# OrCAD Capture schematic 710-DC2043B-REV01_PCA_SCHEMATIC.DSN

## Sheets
1 PAGE2: size Custom; note: LEAD ACID BATTERY BALANCER
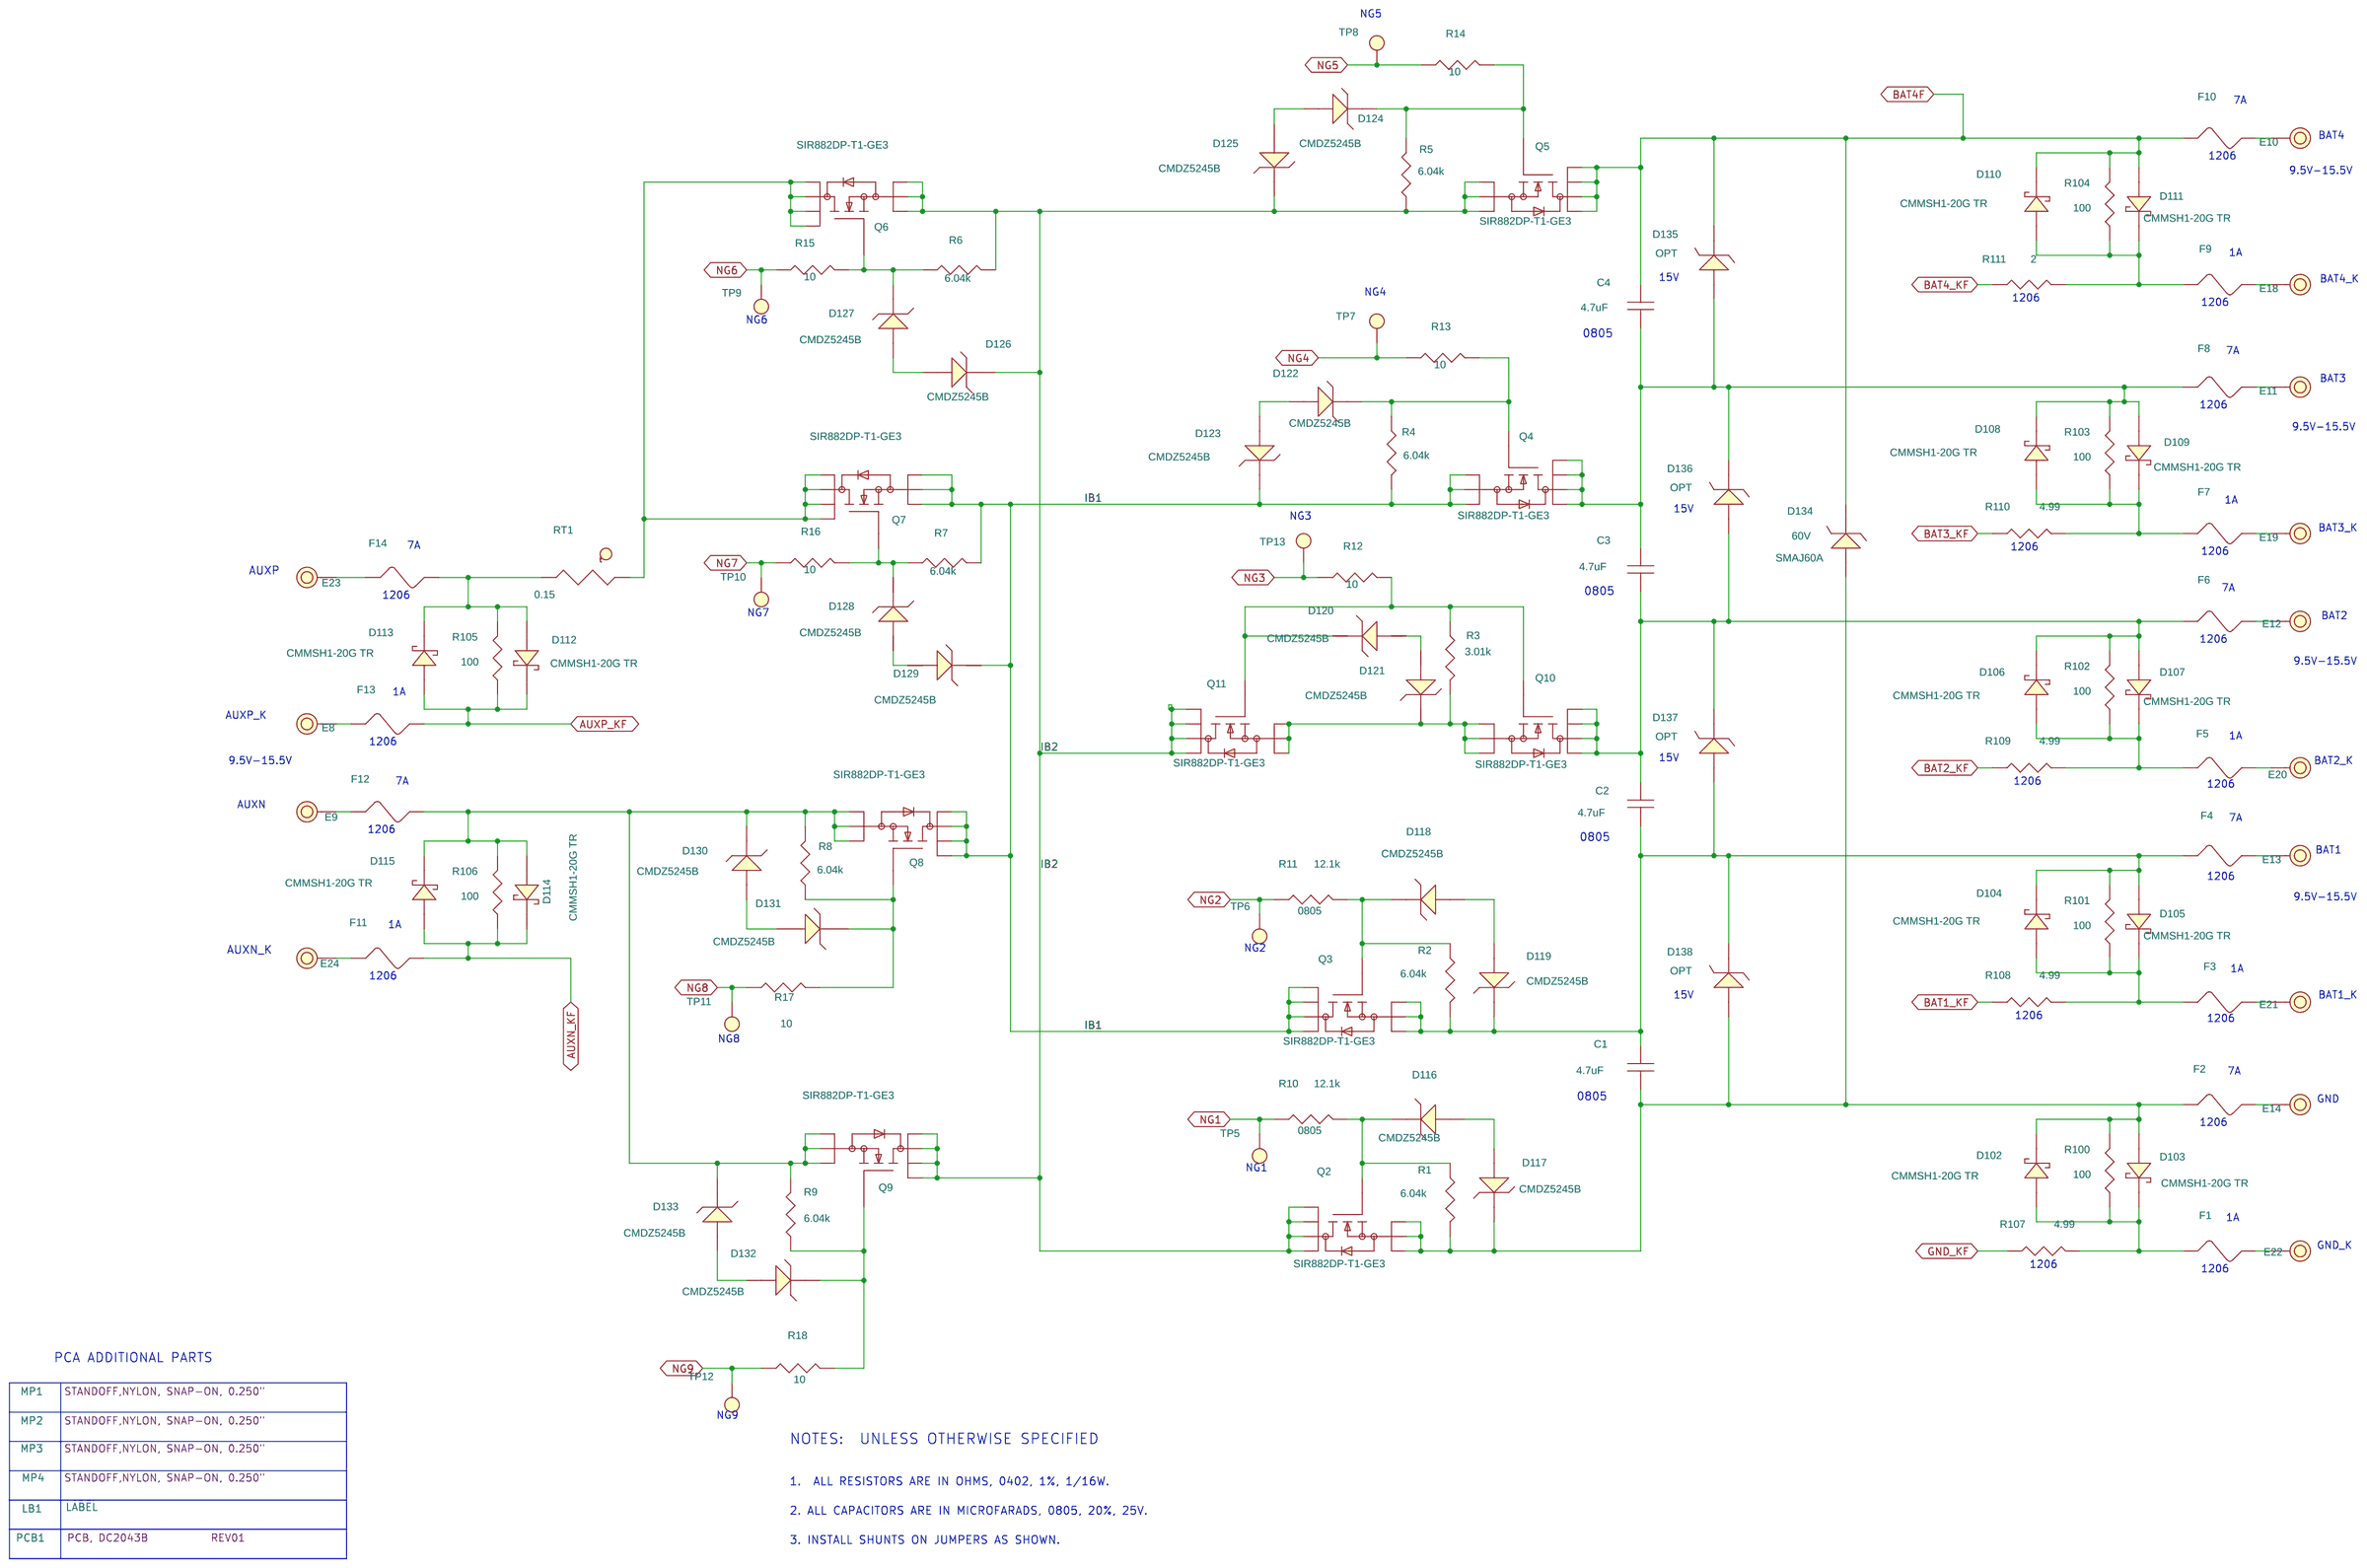
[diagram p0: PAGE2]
2 PAGE1: size Custom
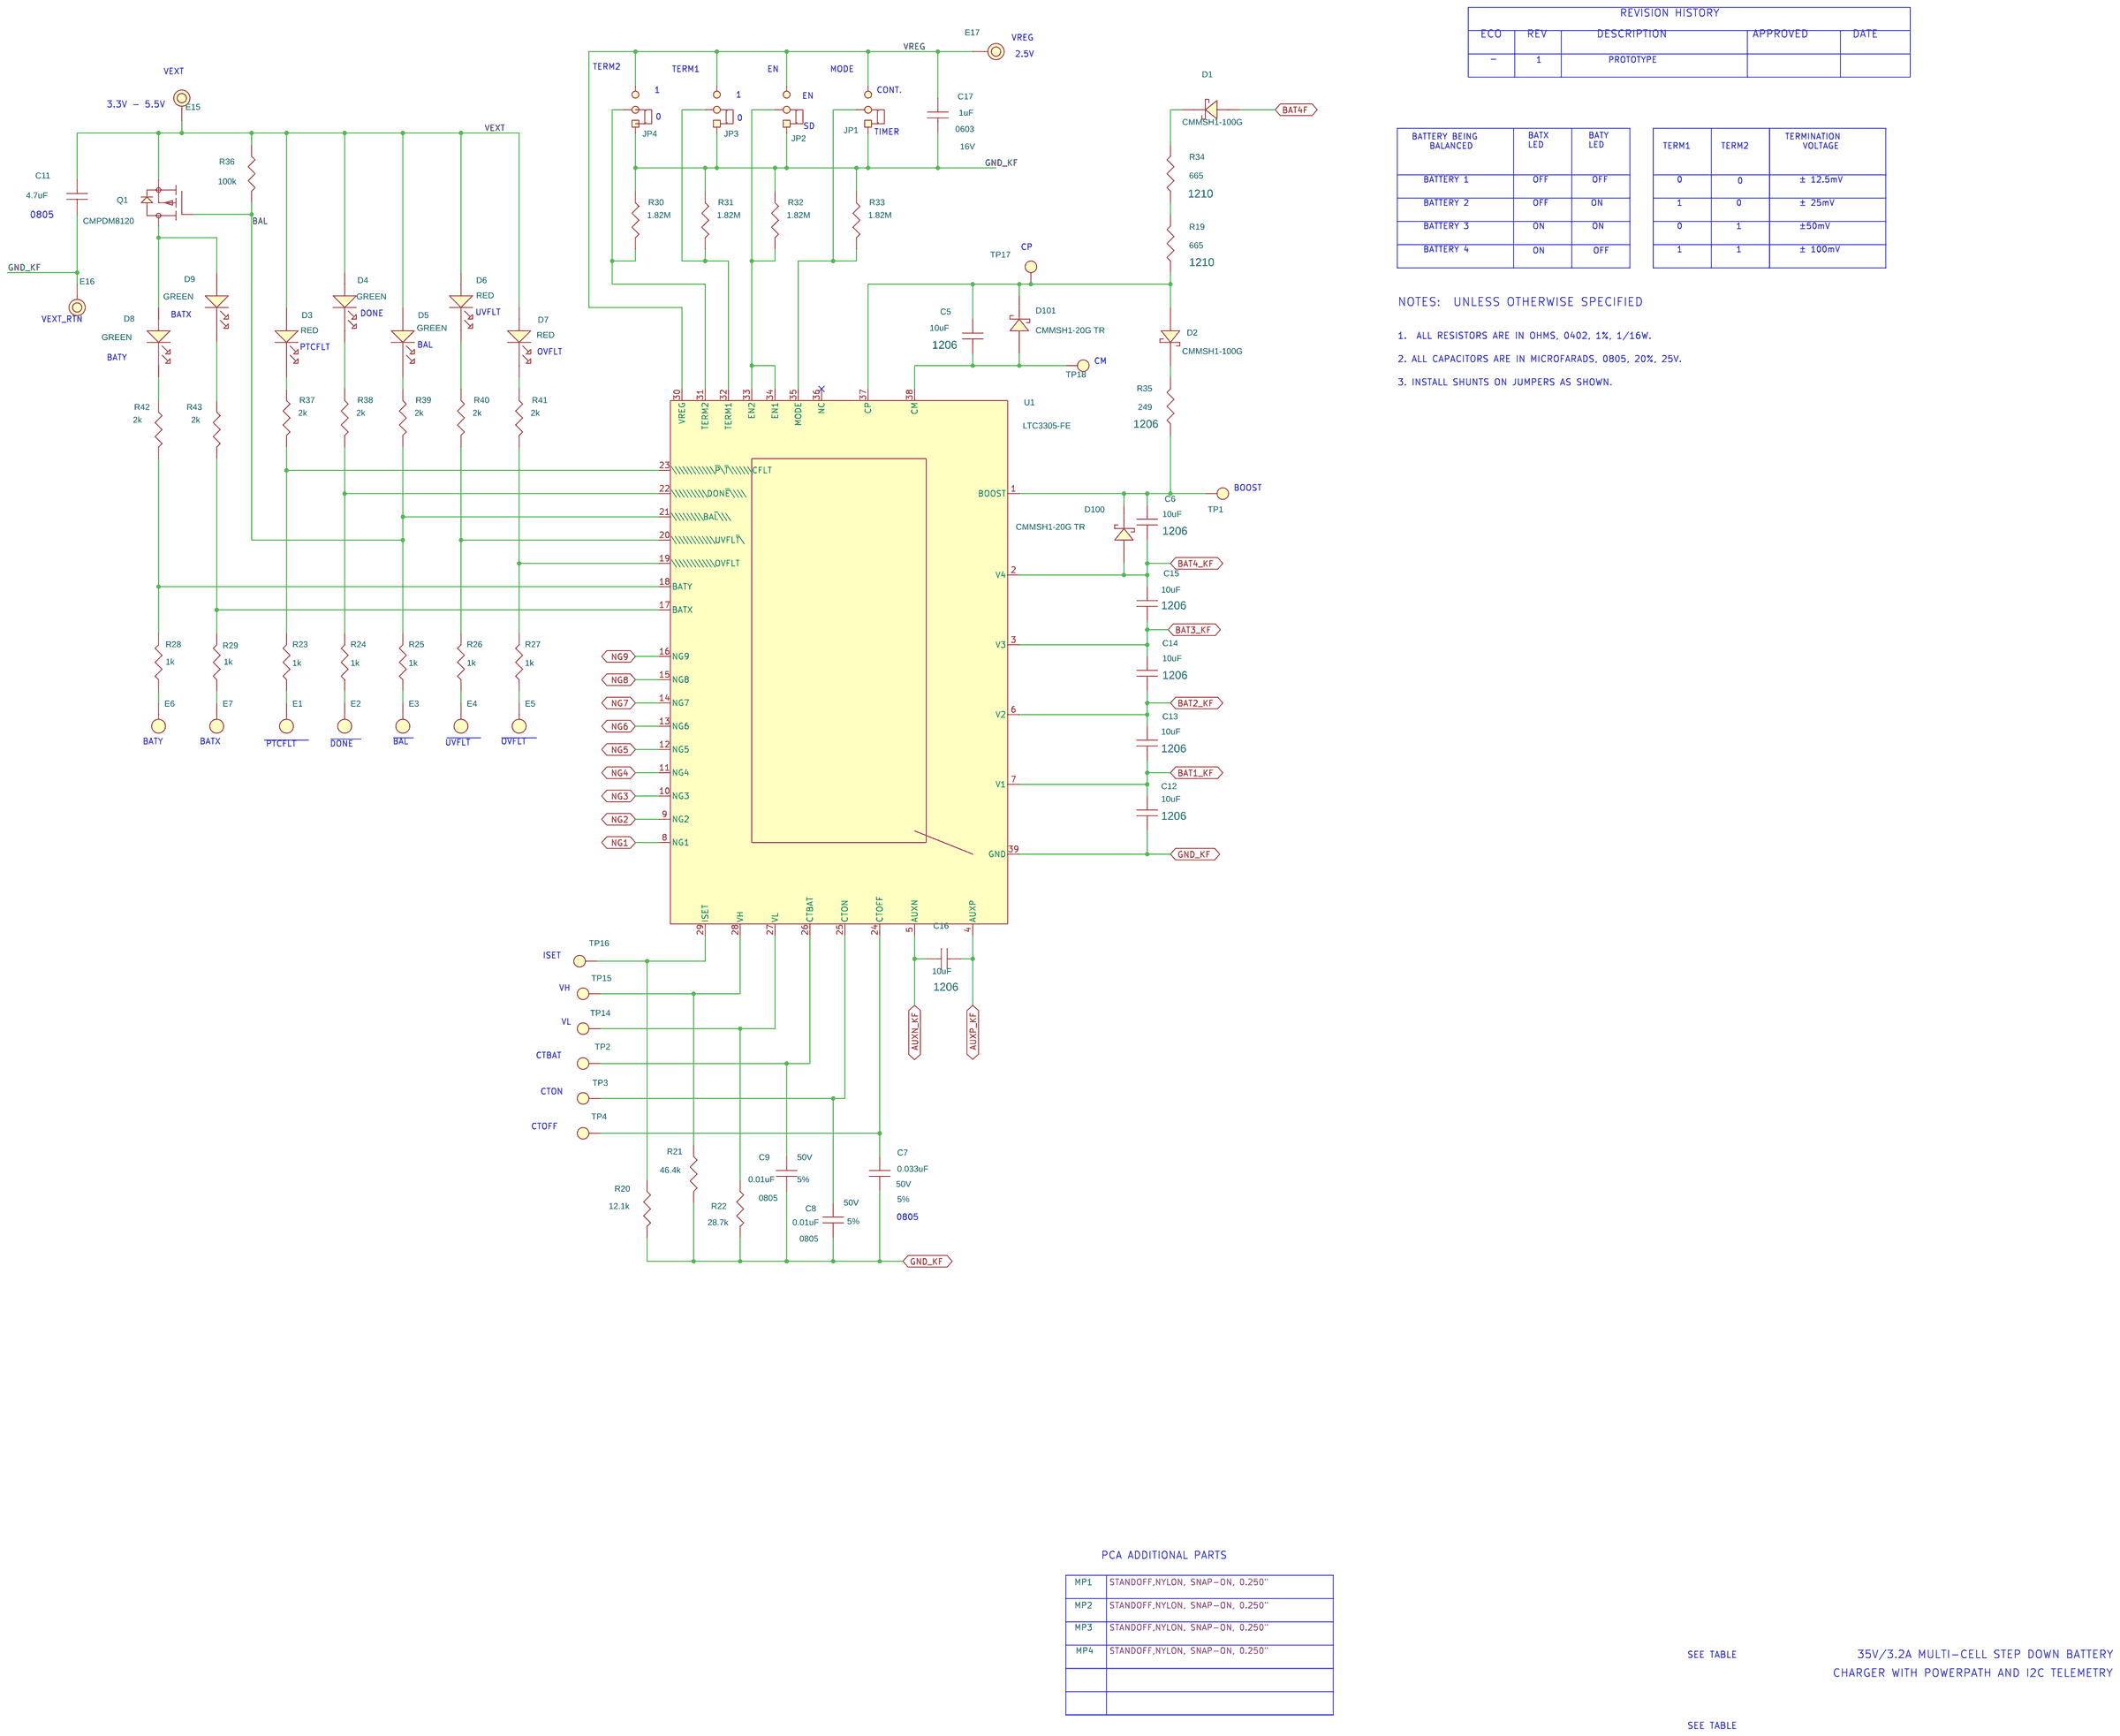
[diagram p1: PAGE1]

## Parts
sheet PAGE1
C5  10uF  [CC1206M]
C6  10uF  [CC1206M]
C7  0.033uF  [CC0805M]
C8  0.01uF  [CC0805M]
C9  0.01uF  [CC0805M]
C11  4.7uF  [CC0805M]
C12  10uF  [CC1206M]
C13  10uF  [CC1206M]
C14  10uF  [CC1206M]
C15  10uF  [CC1206M]
C16  10uF  [CC1206M]
C17  1uF  [CC0603M]
D1  CMMSH1-100G  [SOD-123F]
D2  CMMSH1-100G  [SOD-123F]
D3  RED  [LED-LTST-C193KRKT-5A]
D4  GREEN  [LED-LTST-C193KGKT-5A]
D5  GREEN  [LED-LTST-C193KGKT-5A]
D6  RED  [LED-LTST-C193KRKT-5A]
D7  RED  [LED-LTST-C193KRKT-5A]
D8  GREEN  [LED-LTST-C193KGKT-5A]
D9  GREEN  [LED-LTST-C193KGKT-5A]
D100  CMMSH1-20G TR  [SOD-123F]
D101  CMMSH1-20G TR  [SOD-123F]
E1  TEST POINT  [MILLMAX2308]
E2  TEST POINT  [MILLMAX2308]
E3  TEST POINT  [MILLMAX2308]
E4  TEST POINT  [MILLMAX2308]
E5  TEST POINT  [MILLMAX2308]
E6  TEST POINT  [MILLMAX2308]
E7  TEST POINT  [MILLMAX2308]
E15  TEST POINT  [MILLMAX2501]
E16  TEST POINT  [MILLMAX2501]
E17  TEST POINT  [MILLMAX2501]
JP1  HDR  [HD1X3-079]
JP2  HDR  [HD1X3-079]
JP3  HDR  [HD1X3-079]
JP4  HDR  [HD1X3-079]
MP9  STANDOFF  [MTG-8831]
MP10  STANDOFF  [MTG-8831]
MP11  STANDOFF  [MTG-8831]
MP12  STANDOFF  [MTG-8831]
Q1  CMPDM8120  [SOT-23]
R19  665  [CR1210M]
R20  12.1k  [CR0402M]
R21  46.4k  [CR0402M]
R22  28.7k  [CR0402M]
R23  1k  [CR0402M]
R24  1k  [CR0402M]
R25  1k  [CR0402M]
R26  1k  [CR0402M]
R27  1k  [CR0402M]
R28  1k  [CR0402M]
R29  1k  [CR0402M]
R30  1.82M  [CR0402M]
R31  1.82M  [CR0402M]
R32  1.82M  [CR0402M]
R33  1.82M  [CR0402M]
R34  665  [CR1210M]
R35  249  [CR1206M]
R36  100k  [CR0402M]
R37  2k  [CR0402M]
R38  2k  [CR0402M]
R39  2k  [CR0402M]
R40  2k  [CR0402M]
R41  2k  [CR0402M]
R42  2k  [CR0402M]
R43  2k  [CR0402M]
TP1  TEST PAD  [PADSTYLE7]
TP2  TEST PAD  [PADSTYLE7]
TP3  TEST PAD  [PADSTYLE7]
TP4  TEST PAD  [PADSTYLE7]
TP14  TEST PAD  [PADSTYLE7]
TP15  TEST PAD  [PADSTYLE7]
TP16  TEST PAD  [PADSTYLE7]
TP17  TEST PAD  [PADSTYLE7]
TP18  TEST PAD  [PADSTYLE7]
U1  LTC3305-FE  [LTC-FE-38-1772]
XJP1  SHUNT
XJP2  SHUNT
XJP3  SHUNT
XJP4  SHUNT
sheet PAGE2
C1  4.7uF  [CC0805M]
C2  4.7uF  [CC0805M]
C3  4.7uF  [CC0805M]
C4  4.7uF  [CC0805M]
D102  CMMSH1-20G TR  [SOD-123F]
D103  CMMSH1-20G TR  [SOD-123F]
D104  CMMSH1-20G TR  [SOD-123F]
D105  CMMSH1-20G TR  [SOD-123F]
D106  CMMSH1-20G TR  [SOD-123F]
D107  CMMSH1-20G TR  [SOD-123F]
D108  CMMSH1-20G TR  [SOD-123F]
D109  CMMSH1-20G TR  [SOD-123F]
D110  CMMSH1-20G TR  [SOD-123F]
D111  CMMSH1-20G TR  [SOD-123F]
D112  CMMSH1-20G TR  [SOD-123F]
D113  CMMSH1-20G TR  [SOD-123F]
D114  CMMSH1-20G TR  [SOD-123F]
D115  CMMSH1-20G TR  [SOD-123F]
D116  CMDZ5245B  [CENTRAL-SEMI-SOD-323]
D117  CMDZ5245B  [CENTRAL-SEMI-SOD-323]
D118  CMDZ5245B  [CENTRAL-SEMI-SOD-323]
D119  CMDZ5245B  [CENTRAL-SEMI-SOD-323]
D120  CMDZ5245B  [CENTRAL-SEMI-SOD-323]
D121  CMDZ5245B  [CENTRAL-SEMI-SOD-323]
D122  CMDZ5245B  [CENTRAL-SEMI-SOD-323]
D123  CMDZ5245B  [CENTRAL-SEMI-SOD-323]
D124  CMDZ5245B  [CENTRAL-SEMI-SOD-323]
D125  CMDZ5245B  [CENTRAL-SEMI-SOD-323]
D126  CMDZ5245B  [CENTRAL-SEMI-SOD-323]
D127  CMDZ5245B  [CENTRAL-SEMI-SOD-323]
D128  CMDZ5245B  [CENTRAL-SEMI-SOD-323]
D129  CMDZ5245B  [CENTRAL-SEMI-SOD-323]
D130  CMDZ5245B  [CENTRAL-SEMI-SOD-323]
D131  CMDZ5245B  [CENTRAL-SEMI-SOD-323]
D132  CMDZ5245B  [CENTRAL-SEMI-SOD-323]
D133  CMDZ5245B  [CENTRAL-SEMI-SOD-323]
D134  SMAJ60A  [DIODESINC-SMA]
D135  OPT  [DIODESINC-SMA]
D136  OPT  [DIODESINC-SMA]
D137  OPT  [DIODESINC-SMA]
D138  OPT  [DIODESINC-SMA]
E8  TEST POINT  [MILLMAX2501]
E9  TEST POINT  [MILLMAX2501]
E10  TEST POINT  [MILLMAX2501]
E11  TEST POINT  [MILLMAX2501]
E12  TEST POINT  [MILLMAX2501]
E13  TEST POINT  [MILLMAX2501]
E14  TEST POINT  [MILLMAX2501]
E18  TEST POINT  [MILLMAX2501]
E19  TEST POINT  [MILLMAX2501]
E20  TEST POINT  [MILLMAX2501]
E21  TEST POINT  [MILLMAX2501]
E22  TEST POINT  [MILLMAX2501]
E23  TEST POINT  [MILLMAX2501]
E24  TEST POINT  [MILLMAX2501]
F1  FUSE  [CR1206M]
F2  FUSE  [CR1206M]
F3  FUSE  [CR1206M]
F4  FUSE  [CR1206M]
F5  FUSE  [CR1206M]
F6  FUSE  [CR1206M]
F7  FUSE  [CR1206M]
F8  FUSE  [CR1206M]
F9  FUSE  [CR1206M]
F10  FUSE  [CR1206M]
F11  FUSE  [CR1206M]
F12  FUSE  [CR1206M]
F13  FUSE  [CR1206M]
F14  FUSE  [CR1206M]
LB1  LABEL  [895-0154_REV01]
MP1  STANDOFF  [MTG-8831]
MP2  STANDOFF  [MTG-8831]
MP3  STANDOFF  [MTG-8831]
MP4  STANDOFF  [MTG-8831]
PCB1  PCB, DC2043B
Q2  SIR882DP-T1-GE3  [POWERPAKSO-8]
Q3  SIR882DP-T1-GE3  [POWERPAKSO-8]
Q4  SIR882DP-T1-GE3  [POWERPAKSO-8]
Q5  SIR882DP-T1-GE3  [POWERPAKSO-8]
Q6  SIR882DP-T1-GE3  [POWERPAKSO-8]
Q7  SIR882DP-T1-GE3  [POWERPAKSO-8]
Q8  SIR882DP-T1-GE3  [POWERPAKSO-8]
Q9  SIR882DP-T1-GE3  [POWERPAKSO-8]
Q10  SIR882DP-T1-GE3  [POWERPAKSO-8]
Q11  SIR882DP-T1-GE3  [POWERPAKSO-8]
R1  6.04k  [CR0402M]
R2  6.04k  [CR0402M]
R3  3.01k  [CR0402M]
R4  6.04k  [CR0402M]
R5  6.04k  [CR0402M]
R6  6.04k  [CR0402M]
R7  6.04k  [CR0402M]
R8  6.04k  [CR0402M]
R9  6.04k  [CR0402M]
R10  12.1k  [CR0805M]
R11  12.1k  [CR0805M]
R12  10  [CR0402M]
R13  10  [CR0402M]
R14  10  [CR0402M]
R15  10  [CR0402M]
R16  10  [CR0402M]
R17  10  [CR0402M]
R18  10  [CR0402M]
R100  100  [CR0402M]
R101  100  [CR0402M]
R102  100  [CR0402M]
R103  100  [CR0402M]
R104  100  [CR0402M]
R105  100  [CR0402M]
R106  100  [CR0402M]
R107  4.99  [CR1206M]
R108  4.99  [CR1206M]
R109  4.99  [CR1206M]
R110  4.99  [CR1206M]
R111  2  [CR1206M]
RT1  0.15  [PTC-PTGLASARR27M1B51B0]
TP5  TEST PAD  [PADSTYLE7]
TP6  TEST PAD  [PADSTYLE7]
TP7  TEST PAD  [PADSTYLE7]
TP8  TEST PAD  [PADSTYLE7]
TP9  TEST PAD  [PADSTYLE7]
TP10  TEST PAD  [PADSTYLE7]
TP11  TEST PAD  [PADSTYLE7]
TP12  TEST PAD  [PADSTYLE7]
TP13  TEST PAD  [PADSTYLE7]

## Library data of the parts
C5 C6 C12-C16 = CAP: CAP.,10uF,X7R,25V,20%,1206; CLASS: DISCRETE; Dielectric Type: X7R; FPLIST: CC1206N,CC1206L,CC1206M; Manufacturer: TDK; Manufacturer PN: C3216X7R1E106M160AB; PART_NUMBER: 150-2302; Package Size: 1206; Rated Voltage: 25V; Tolerance: 20%
C7 = CAP: CAP.,0.033uF,C0G,50V,5%,0805,AUTOMOTIVE; CLASS: DISCRETE; Dielectric Type: C0G; FPLIST: CC0805N,CC0805L,CC0805M; Manufacturer: TDK; Manufacturer PN: CGA4J2C0G1H333J125AA; PART_NUMBER: 150-2300; Package Size: 0805; Package Type: Surface Mount, MLCC; Rated Voltage: 50V; Temperature Coefficient: C0G, NP0; Tolerance: 5%; UserField01: AUTOMOTIVE
C8 C9 = CAP: CAP.,0.01uF,C0G,50V,5%,0805,AUTOMOTIVE; CLASS: DISCRETE; Dielectric Type: C0G; FPLIST: CC0805N,CC0805L,CC0805M; Manufacturer: TDK; Manufacturer PN: CGA4C2C0G1H103J060AA; PART_NUMBER: 150-2301; Package Size: 0805; Package Type: SMD; Rated Voltage: 50V; Tolerance: 5%; UserField01: AUTOMOTIVE
C1-C4 C11 = CAP: CAP.,4.7uF,X7R,25V,10%,0805; CLASS: DISCRETE; Dielectric Type: X7R; FPLIST: CC0805N,CC0805L,CC0805M; Manufacturer: MURATA; Manufacturer PN: GRM21BR71E475KA73L; PART_NUMBER: 150-3337; Package Size: 0805; Rated Voltage: 25V; Tolerance: 10%
C17 = CAP: CAP.,1uF,X7R,16V,10%,0603; CLASS: DISCRETE; Dielectric Type: X7R; FPLIST: CC0603N,CC0603L,CC0603M; Manufacturer: MURATA; Manufacturer PN: GRM188R71C105KA12D; PART_NUMBER: 150-0179; Package Size: 0603; Rated Voltage: 16V; Tolerance: 10%
D1 D2 = DIODE_SCHOTTKY_A_ALT: DIODE,SCHOTTKY,100V,1A,SOD-123F; CLASS: DISCRETE; Manufacturer: CENTRAL SEMI; Manufacturer PN: CMMSH1-100G TR LEAD FREE; PART_NUMBER: 210-0147; Rated Voltage: 100V
D3 D6 D7 = LED_ALT: LED,RED,CLEAR,0603 SMD; CLASS: DISCRETE; Manufacturer: LITE-ON TECHNOLOGY CORP; Manufacturer PN: LTST-C193KRKT-5A; PART_NUMBER: 270-0070; Package Size: 0603 (1608 Metric)
D4 D5 D8 D9 = LED_ALT: LED,GREEN,CLEAR,0603 SMD; CLASS: DISCRETE; Manufacturer: LITE-ON TECHNOLOGY CORP; Manufacturer PN: LTST-C193KGKT-5A; PART_NUMBER: 270-0054; Package Size: 0603 (1608 Metric)
D100-D115 = DIODE_SCHOTTKY_A_ALT: DIODE,SCHOTTKY,20V,1A,SOD-123F; CLASS: DISCRETE; Manufacturer: CENTRAL SEMI; Manufacturer PN: CMMSH1-20G TR LEAD FREE; PART_NUMBER: 210-0222; Rated Voltage: 20V
E1-E7 = TEST_POINT_.156_MILL-MAX_2308: TEST POINT,TURRET,0.064" MTG. HOLE,0.125" THICK PCB; CLASS: IO; Manufacturer: MILL-MAX; Manufacturer PN: 2308-4-00-80-00-00-07-0; PART_NUMBER: 260-0008
E8-E24 = TESTPOINT_.219_MILL-MAX_2501: TEST POINT,TURRET,0.094",MTG. HOLE; CLASS: IO; Manufacturer: MILL-MAX; Manufacturer PN: 2501-2-00-80-00-00-07-0; PART_NUMBER: 260-0003
JP1-JP4 = 3_PIN_HEADER_.079_SINGLE_ROW_D: CONN.,HDR,MALE,1x3,2mm,THT, STR; CLASS: IO; Manufacturer: Wurth Elektronik; Manufacturer PN: 62000311121; PART_NUMBER: 250-0484
MP1-MP4 MP9-MP12 = BLANK_MECHANICAL_PART: STANDOFF,NYLON, SNAP-ON, 0.250"; CLASS: MECHANICAL PART; Manufacturer: KEYSTONE; Manufacturer PN: 8831; PART_NUMBER: 763-0006
Q1 = CMPDM8120: XSTR.,MOSFET, P-CH,20V,0.95A,SOT-23; CLASS: DISCRETE; Manufacturer: CENTRAL SEMI; Manufacturer PN: CMPDM8120 PBFREE; PART_NUMBER: 240-0228
R19 R34 = RES: RES.,665 OHMS,1%,1/2W,1210; CLASS: DISCRETE; FPLIST: CR1210N,CR1210L,CR1210M; Manufacturer: VISHAY; Manufacturer PN: CRCW1210665RFKEA; PART_NUMBER: 100-0544; Package Size: 1210; Rated Power: 1/2W; Temperature Coefficient: 100ppm; Tolerance: 1%
R20 = RES: RES.,12.1k OHMS,1%,1/16W,0402; CLASS: DISCRETE; FPLIST: CR0402N,CR0402L,CR0402M; Manufacturer: VISHAY; Manufacturer PN: CRCW040212K1FKED; PART_NUMBER: 100-2639; Package Size: 0402; Rated Power: 1/16W; Temperature Coefficient: 100ppm/C; Tolerance: 1%
R21 = RES: RES.,46.4k OHMS,1%,1/16W,0402; CLASS: DISCRETE; FPLIST: CR0402N,CR0402L,CR0402M; Manufacturer: VISHAY; Manufacturer PN: CRCW040246K4FKED; PART_NUMBER: 100-2065; Package Size: 0402; Rated Power: 1/16W; Temperature Coefficient: +/-100PPM; Tolerance: 1%
R22 = RES: RES.,28.7k OHMS,1%,1/16W,0402; CLASS: DISCRETE; FPLIST: CR0402N,CR0402L,CR0402M; Manufacturer: VISHAY; Manufacturer PN: CRCW040228K7FKED; PART_NUMBER: 100-0545; Package Size: 0402; Rated Power: 1/16W; Temperature Coefficient: 100ppm; Tolerance: 1%
R23-R29 = RES: RES.,1k OHM,1%,1/16W,0402; CLASS: DISCRETE; FPLIST: CR0402N,CR0402L,CR0402M; Manufacturer: NIC; Manufacturer PN: NRC04F1001TRF; PART_NUMBER: 100-2456; Package Size: 0402; Rated Power: 1/16W; Temperature Coefficient: 100ppm/C; Tolerance: 1%
R30-R33 = RES: RES.,1.82M OHMS,1%,1/16W,0402; CLASS: DISCRETE; FPLIST: CR0402N,CR0402L,CR0402M; Manufacturer: NIC; Manufacturer PN: NRC04F1824TRF; PART_NUMBER: 100-0446; Package Size: 0402; Rated Power: 1/16W; Tolerance: 1%
R35 = RES: RES.,249 OHMS,1%,1/4W,1206; CLASS: DISCRETE; FPLIST: CR1206N,CR1206L,CR1206M; Manufacturer: VISHAY; Manufacturer PN: CRCW1206249RFKEA; PART_NUMBER: 100-0546; Package Size: 1206; Rated Power: 1/4W; Temperature Coefficient: 100ppm; Tolerance: 1%
R36 = RES: RES.,100k OHMS,1%,1/16W,0402; CLASS: DISCRETE; FPLIST: CR0402N,CR0402L,CR0402M; Manufacturer: NIC; Manufacturer PN: NRC04F1003TRF; PART_NUMBER: 100-2396; Package Size: 0402; Rated Power: 1/16W; Temperature Coefficient: 100ppm; Tolerance: 1%
R37-R43 = RES: RES.,2k OHMS,1%,1/16W,0402; CLASS: DISCRETE; FPLIST: CR0402N,CR0402L,CR0402M; Manufacturer: NIC; Manufacturer PN: NRC04F2001TRF; PART_NUMBER: 100-0018; Package Size: 0402; Rated Power: 1/16W; Temperature Coefficient: 100ppm/C; Tolerance: 1%
TP1-TP18 = PAD_STYLE_E: TESTPOINT, PCB COPPER FEATURE; CLASS: IO; FPLIST: PADSTYLE1,PADSTYLE2,PADSTYLE3,PADSTYLE4,PADSTYLE5,PADSTYLE6,PADSTYLE7,PADSTYLE8; PART_NUMBER: PCBPADS-8
U1 = LTC3305-FE: IC,LEAD ACID BATTERY BALANCER,TSSOP-38; CLASS: IC; Manufacturer: LINEAR TECHNOLOGY; Manufacturer PN: LTC3305EFE#PBF; PART_NUMBER: LTC3305EFE#PBF; Package Type: TSSOP-38
XJP1-XJP4 = CONN_SHUNT_2_POS_2mm: CONN.,SHUNT,FEMALE,2 POS,2mm; CLASS: IO; Manufacturer: Wurth Elektronik; Manufacturer PN: 60800213421; PART_NUMBER: 250-0485
D116-D133 = ZENER_ALT: DIODE,ZENER,15V,250mW,SOD-323; CLASS: DISCRETE; Manufacturer: CENTRAL SEMI; Manufacturer PN: CMDZ5245B TR LEAD FREE; PART_NUMBER: 210-0223; Package Size: SC-76, SOD-323; Rated Power: 250mW; Rated Voltage: 15V
D134 = DIODE_TVS_B_ALT: DIODE, TVS, 60V, 400W, SMA; CLASS: DISCRETE; FPLIST: SMA,DIODESINC-SMA; Manufacturer: DIODES INC.; Manufacturer PN: SMAJ60A-13-F; PART_NUMBER: 210-0140; Rated Voltage: 60V
D135-D138 = DIODE_TVS_B_ALT: TVS DIODE 15VWM 24.4VC SMA; CLASS: DISCRETE; FPLIST: SMA,DIODESINC-SMA; Manufacturer: Diodes Incorporated; Manufacturer PN: SMAJ15A-13-F; PART_NUMBER: TMP-1548; Package Size: DO-214AC, SMA
F1 F3 F5 F7 F9 F11 F13 = FUSE: FUSE,BOARD MNT,1A,32VAC,63VDC,1206; CLASS: DISCRETE; Manufacturer: Eaton; Manufacturer PN: TR/3216FF1-R; PART_NUMBER: 120-0043; Package Size: 0.126" L x 0.063" W x 0.035" H (3.20mm x 1.60mm x 0.89mm)
F2 F4 F6 F8 F10 F12 F14 = FUSE: FUSE,BOARD MNT,7A,32VAC/VDC,1206; CLASS: DISCRETE; Manufacturer: Eaton; Manufacturer PN: TR/3216FF7-R; PART_NUMBER: 120-0044; Package Size: 0.126" L x 0.063" W x 0.035" H (3.20mm x 1.60mm x 0.89mm)
LB1 = BLANK_LABEL: LABEL SPEC, DEMO BOARD SERIAL NUMBER; Manufacturer: BRADY; Manufacturer PN: THT-96-717-10; PART_NUMBER: 895-0154
PCB1 = BLANK_PCB_PART: BOM Notes: REV01; CLASS: DISCRETE; Manufacturer: EAGLE ELECTRONICS, INC; Manufacturer PN: 600-DC2043B; PART_NUMBER: 600-DC2043B
Q2-Q11 = SIR882DP-T1-GE3: XSTR.,MOSFET, N-CH,100V,60A,PPAK SO-8; CLASS: DISCRETE; Manufacturer: VISHAY; PART_NUMBER: 240-0026; Package Size: PowerPAK® SO-8; Package Type: PPAK SO-8; Polarity: MOSFET N-Channel, Metal Oxide; Rated Power: 83W
R1 R2 R4-R9 = RES: RES.,6.04k OHMS,1%,1/16W,0402; CLASS: DISCRETE; FPLIST: CR0402N,CR0402L,CR0402M; Manufacturer: VISHAY; Manufacturer PN: CRCW04026K04FKED; PART_NUMBER: 100-0542; Package Size: 0402; Rated Power: 1/16W; Temperature Coefficient: 100ppm; Tolerance: 1%
R3 = RES: RES.,3.01k OHMS,1%,1/16W,0402; CLASS: DISCRETE; FPLIST: CR0402N,CR0402L,CR0402M; Manufacturer: VISHAY; Manufacturer PN: CRCW04023K01FKED; PART_NUMBER: 100-0028; Package Size: 0402; Rated Power: 1/16W; Temperature Coefficient: 100ppm/C; Tolerance: 1%
R10 R11 = RES: RES.,12.1k OHMS,1%,1/8W,0805; CLASS: DISCRETE; FPLIST: CR0805N,CR0805L,CR0805M; Manufacturer: VISHAY; Manufacturer PN: CRCW080512K1FKEA; PART_NUMBER: 100-0543; Package Size: 0805; Rated Power: 1/8W; Temperature Coefficient: 100ppm; Tolerance: 1%
R12-R18 = RES: RES.,10 OHMS,1%,1/16W,0402; CLASS: DISCRETE; FPLIST: CR0402N,CR0402L,CR0402M; Manufacturer: VISHAY; Manufacturer PN: CRCW040210R0FKED; PART_NUMBER: 100-0325; Package Size: 0402; Rated Power: 1/16W; Temperature Coefficient: 100ppm; Tolerance: 1%
R100-R106 = RES: RES.,100 OHMS,1%,1/16W,0402; CLASS: DISCRETE; FPLIST: CR0402N,CR0402L,CR0402M; Manufacturer: KOA SPEER; Manufacturer PN: RK73H1ETTP1000F; PART_NUMBER: 100-0175; Package Size: 0402; Rated Power: 1/16W; Temperature Coefficient: 100ppm/C; Tolerance: 1%
R107-R110 = RES: RES.,PULSE PROOF,4.99 OHMS,1%,1/2W,1206; CLASS: DISCRETE; FPLIST: CR1206N,CR1206L,CR1206M; Manufacturer: VISHAY; Manufacturer PN: CRCW12064R99FKEAHP; PART_NUMBER: 100-0547; Package Size: 1206; Rated Power: 1/2W; Temperature Coefficient: 100ppm; Tolerance: 1%
R111 = RES: RES.,PULSE PROOF,2 OHMS,1%,1/2W,1206; CLASS: DISCRETE; FPLIST: CR1206N,CR1206L,CR1206M; Manufacturer: VISHAY; Manufacturer PN: CRCW12062R00FKEAHP; PART_NUMBER: 100-0548; Package Size: 1206; Rated Power: 1/2W; Temperature Coefficient: 100ppm; Tolerance: 1%
RT1 = THERMISTOR: RES.,THERMISTOR PTC, AUTOMOTIVE,0.15 OHM,20%,2.3W,THT; CLASS: DISCRETE; Manufacturer: MURATA; Manufacturer PN: PTGLESARR15M1B51B0; PART_NUMBER: 122-0004; Package Size: THT; Rated Power: 2.3W; Tolerance: 20%

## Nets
GND_KF: C7.2 C8.2 C9.2 C11.2 C12.2 C17.2 E16.1 JP1.1 JP2.1 JP3.1 JP4.1 R20.2 R21.2 R22.2 R30.1 R31.1 R32.1 R33.1 R107.1 U1.39(GND)
AUXN_KF: C16.2 D114.1(C) D115.2(A) F11.2 R106.1 U1.5(AUXN)
AUXP_KF: C16.1 D112.1(C) D113.2(A) F13.2 R105.1 U1.4(AUXP)
BAL: Q1.1(G) R25.1 R36.2 R39.2 U1.21(\\\\\\\\BA~{L}\\\)
BAT1_KF: C12.1 C13.2 R108.1 U1.7(V1)
BAT2_KF: C13.1 C14.2 R109.1 U1.6(V2)
BAT3_KF: C14.1 C15.2 R110.1 U1.3(V3)
BAT4_KF: C6.2 C15.1 D100.2(A) R111.1 U1.2(V4)
BAT4F: C4.1 D1.2(A) D110.1(C) D111.2(A) D134.1(C) D135.1(C) F10.1 Q5.5(D) Q5.6(D) Q5.7(D) Q5.8(D) R104.2
IB1: D123.1(C) D129.1(C) Q3.5(D) Q3.6(D) Q3.7(D) Q3.8(D) Q4.1(S) Q4.2(S) Q4.3(S) Q7.1(S) Q7.2(S) Q7.3(S) Q8.5(D) Q8.6(D) Q8.7(D) Q8.8(D) R4.2 R7.2
IB2: D125.1(C) D126.1(C) Q2.5(D) Q2.6(D) Q2.7(D) Q2.8(D) Q5.1(S) Q5.2(S) Q5.3(S) Q6.1(S) Q6.2(S) Q6.3(S) Q9.5(D) Q9.6(D) Q9.7(D) Q9.8(D) Q11.5(D) Q11.6(D) Q11.7(D) Q11.8(D) R5.1 R6.2
NG1: R10.1 TP5.1(TP) U1.8(NG1)
NG2: R11.1 TP6.1(TP) U1.9(NG2)
NG3: R12.1 TP13.1(TP) U1.10(NG3)
NG4: R13.1 TP7.1(TP) U1.11(NG4)
NG5: R14.1 TP8.1(TP) U1.12(NG5)
NG6: R15.1 TP9.1(TP) U1.13(NG6)
NG7: R16.1 TP10.1(TP) U1.14(NG7)
NG8: R17.1 TP11.1(TP) U1.15(NG8)
NG9: R18.1 TP12.1(TP) U1.16(NG9)
VEXT: C11.1 D3.2(ANODE) D4.2(ANODE) D5.2(ANODE) D6.2(ANODE) D7.2(ANODE) E15.1 Q1.2(S) R36.1
VREG: C17.1 E17.1 JP1.3 JP2.3 JP3.3 JP4.3 U1.30(VREG)
N18160: JP4.2 R30.2 U1.31(TERM2)
N18397: JP3.2 R31.2 U1.32(TERM1)
N18417: JP2.2 R32.2 U1.33(EN2) U1.34(EN1)
N18794: JP1.2 R33.2 U1.35(MODE)
N19939: C5.1 D2.2(A) D101.1(C) R19.1 TP17.1(TP) U1.37(CP)
N20071: C5.2 D101.2(A) TP18.1(TP) U1.38(CM)
N16608069: R24.1 R38.2 U1.22(\\\\\\\\\DON~{E}\\\\)
N16609341: R28.1 R42.2 U1.18(BATY)
N17749658: C3.1 C4.2 D108.1(C) D109.2(A) D135.2(A) D136.1(C) F8.1 Q4.5(D) Q4.6(D) Q4.7(D) Q4.8(D) R103.2
N17749666: C2.1 C3.2 D106.1(C) D107.2(A) D136.2(A) D137.1(C) F6.1 Q10.5(D) Q10.6(D) Q10.7(D) Q10.8(D) R102.2
N17749672: C1.1 C2.2 D104.1(C) D105.2(A) D119.1(C) D137.2(A) D138.1(C) F4.1 Q3.1(S) Q3.2(S) Q3.3(S) R2.2 R101.2
N17749674: C1.2 D102.1(C) D103.2(A) D117.1(C) D134.2(A) D138.2(A) F2.1 Q2.1(S) Q2.2(S) Q2.3(S) R1.2 R100.2
N17749678: D116.1(C) Q2.4(G) R1.1 R10.2
N17749680: D118.1(C) Q3.4(G) R2.1 R11.2
N17749683: D120.1(C) Q10.4(G) Q11.4(G) R3.1 R12.2
N17749685: D122.1(C) Q4.4(G) R4.1 R13.2
N17749686: D121.1(C) Q10.1(S) Q10.2(S) Q10.3(S) Q11.1(S) Q11.2(S) Q11.3(S) R3.2
N17749697: D124.1(C) Q5.4(G) R5.2 R14.2
N17749752: D127.1(C) Q6.4(G) R6.1 R15.2
N17749784: D128.1(C) Q7.4(G) R7.1 R16.2
N17749788: D131.1(C) Q8.4(G) R8.1 R17.2
N17749791: D132.1(C) Q9.4(G) R9.1 R18.2
N17749806: Q6.5(D) Q6.6(D) Q6.7(D) Q6.8(D) Q7.5(D) Q7.6(D) Q7.7(D) Q7.8(D) RT1.2
N17749808: D114.2(A) D115.1(C) D130.1(C) D133.1(C) F12.2 Q8.1(S) Q8.2(S) Q8.3(S) Q9.1(S) Q9.2(S) Q9.3(S) R8.2 R9.2 R106.2
N17757197: C6.1 D100.1(C) R35.1 TP1.1(TP) U1.1(BOOST)
N17771518: D110.2(A) D111.1(C) F9.1 R104.1 R111.2
N17772584: D102.2(A) D103.1(C) F1.1 R100.1 R107.2
N17772667: D112.2(A) D113.1(C) F14.2 R105.2 RT1.1
N17773859: D124.2(A) D125.2(A)
N17774130: D122.2(A) D123.2(A)
N17775676: D126.2(A) D127.2(A)
N17775862: D128.2(A) D129.2(A)
N17792962: R23.1 R37.2 U1.23(\\\\\\\\\\\~{P}\~{T}\\\\\\CFLT)
N17806849: E23.1 F14.1
N17813247: E24.1 F11.1
N17814468: E18.1 F9.2
N17814677: E19.1 F7.2
N17814777: D108.2(A) D109.1(C) F7.1 R103.1 R110.2
N17815028: E20.1 F5.2
N17815064: E12.1 F6.2
N17815177: D106.2(A) D107.1(C) F5.1 R102.1 R109.2
N17815799: E21.1 F3.2
N17815864: E13.1 F4.2
N17815985: D104.2(A) D105.1(C) F3.1 R101.1 R108.2
N17819605: E11.1 F8.2
N17821017: E14.1 F2.2
N17821175: E22.1 F1.2
N17821876: E8.1 F13.1
N17821892: E9.1 F12.1
N17826430: D120.2(A) D121.2(A)
N17827845: D130.2(A) D131.2(A)
N17828639: D132.2(A) D133.2(A)
N17829434: D116.2(A) D117.2(A)
N17830350: D118.2(A) D119.2(A)
N17841520: R29.1 R43.2 U1.17(BATX)
N17841522: D8.2(ANODE) D9.2(ANODE) Q1.3(D)
N17841585: D8.1(CATHODE) R42.1
N17841658: D9.1(CATHODE) R43.1
N17841851: E1.1(A) R23.2
N17841854: E2.1(A) R24.2
N17841857: E3.1(A) R25.2
N17841860: E4.1(A) R26.2
N17841863: E5.1(A) R27.2
N17841914: R27.1 R41.2 U1.19(\\\\\\\\\\\OVFLT)
N17841927: R26.1 R40.2 U1.20(\\\\\\\\\\\UVFL~{T}\)
N17842061: D7.1(CATHODE) R41.1
N17842146: D6.1(CATHODE) R40.1
N17842238: D5.1(CATHODE) R39.1
N17842333: D4.1(CATHODE) R38.1
N17842413: D3.1(CATHODE) R37.1
N17842632: E7.1(A) R29.2
N17842641: E6.1(A) R28.2
N17846683: R20.1 TP16.1(TP) U1.29(ISET)
N17846796: R21.1 TP15.1(TP) U1.28(VH)
N17846798: R22.1 TP14.1(TP) U1.27(VL)
N17848041: C9.1 TP2.1(TP) U1.26(CTBAT)
N17848709: C8.1 TP3.1(TP) U1.25(CTON)
N17849430: C7.1 TP4.1(TP) U1.24(CTOFF)
N17855474: R19.2 R34.1
N17865828: E10.1 F10.2
N17983022: D1.1(C) R34.2
N17983043: D2.1(C) R35.2

Not connected (* = marked no-connect by the designer): U1 36(NC)*

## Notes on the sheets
sheet 1
- NG5
- 7A
- BAT4
- 1206
- 9.5V-15.5V
- 1A
- NG4
- 15V
- BAT4_K
- 1206
- 1206
- NG6
- 0805
- 7A
- BAT3
- 1206
- 9.5V-15.5V
- 1A
- NG3
- 15V
- BAT3_K
- 7A
- 1206
- 1206
- AUXP
- 1206
- 0805
- 7A
- NG7
- BAT2
- 1206
- 9.5V-15.5V
- 1A
- AUXP_K
- 1206
- 1A
- 15V
- 9.5V-15.5V
- BAT2_K
- 7A
- 1206
- 1206
- AUXN
- 1206
- 7A
- 0805
- BAT1
- 1206
- 9.5V-15.5V
- 1A
- AUXN_K
- NG2
- 1206
- 1A
- 15V
- BAT1_K
- 1206
- 1206
- NG8
- 7A
- 0805
- GND
- 1206
- NG1
- 1A
- GND_K
- 1206
- 1206
- PCA ADDITIONAL PARTS
- NG9
- NOTES:  UNLESS OTHERWISE SPECIFIED
- 1.  ALL RESISTORS ARE IN OHMS, 0402, 1%, 1/16W.
- 2. ALL CAPACITORS ARE IN MICROFARADS, 0805, 20%, 25V.
- 3. INSTALL SHUNTS ON JUMPERS AS SHOWN.
sheet 2
- REVISION HISTORY
- VREG
- ECO
- REV
- DESCRIPTION
- APPROVED
- DATE
- 2.5V
- TERM2
- -
- 1
- PROTOTYPE
- VEXT
- TERM1
- EN
- MODE
- 1
- 1
- CONT.
- 3.3V - 5.5V
- EN
- 0
- 0
- SD
- TIMER
- BATTERY BEING
      BALANCED
- BATX
  LED
- BATY
  LED
- TERMINATION
      VOLTAGE
- TERM1
- TERM2
- BATTERY 1
- OFF
- OFF
- 0
- 0
- ± 12.5mV
- BATTERY 2
- OFF
- ON
- 1
- 0
- ± 25mV
- 0805
- BATTERY 3
- ON
- ON
- 0
- 1
- ±50mV
- CP
- BATTERY 4
- ON
- OFF
- 1
- 1
- ± 100mV
- NOTES:  UNLESS OTHERWISE SPECIFIED
- BATX
- DONE
- UVFLT
- VEXT_RTN
- 1.  ALL RESISTORS ARE IN OHMS, 0402, 1%, 1/16W.
- PTCFLT
- BAL
- OVFLT
- BATY
- CM
- 2. ALL CAPACITORS ARE IN MICROFARADS, 0805, 20%, 25V.
- 3. INSTALL SHUNTS ON JUMPERS AS SHOWN.
- BOOST
- BATY
- BATX
- PTCFLT
- DONE
- BAL
- UVFLT
- OVFLT
- ISET
- VH
- VL
- CTBAT
- CTON
- CTOFF
- 0805
- PCA ADDITIONAL PARTS
- SEE TABLE
- 35V/3.2A MULTI-CELL STEP DOWN BATTERY
- CHARGER WITH POWERPATH AND I2C TELEMETRY
- SEE TABLE
